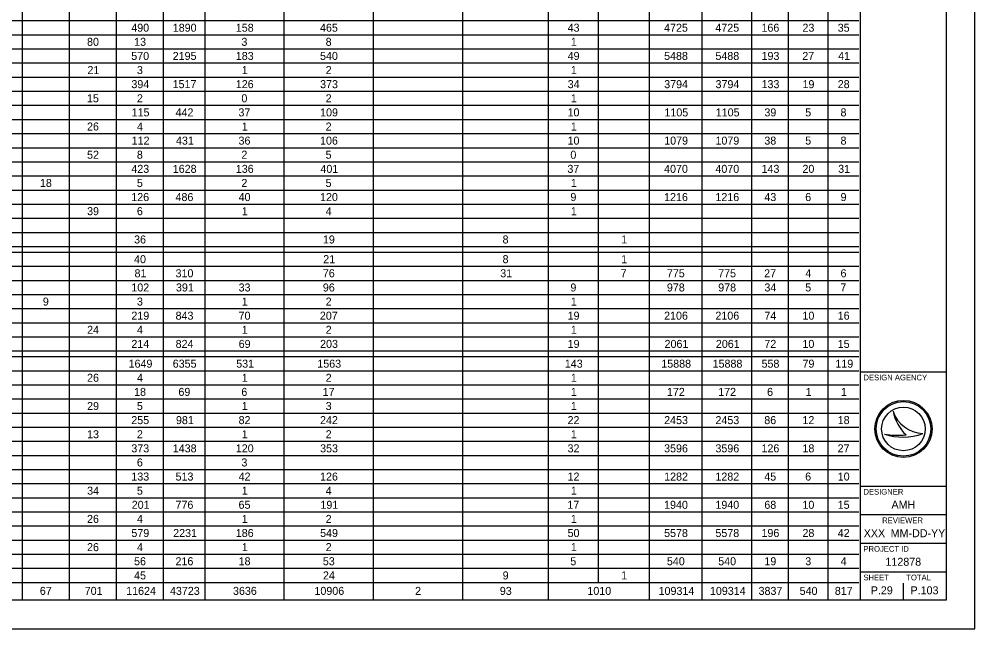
# Model space of a CAD drawing. Extents: x 0 to 34, y 0 to 22.
# Drawn here: x 17.28 to 34, y 0 to 10.67 of the extents above; entities that cross this region are included whole.
import ezdxf

# ---------------------------------------------------------------- set-up
doc = ezdxf.new("R2010")
doc.units = 0
for name, color, linetype in [('SH_Border', 7, 'Continuous'), ('SH_Cut_Line', 7, 'Continuous'), ('SH_Data', 7, 'Continuous'), ('SH_Text', 7, 'Continuous')]:
    doc.layers.add(name, color=color, linetype=linetype)

msp = doc.modelspace()

# ---------------------------------------------------------------- linework, layer by layer
at = {"layer": 'SH_Border'}
for p, q in [((32, 0.5), (32, 21.5)), ((32, 4.5), (33.5, 4.5)), ((32, 2.5), (33.5, 2.5)), ((32, 2), (33.5, 2)), ((32, 1.5), (33.5, 1.5)), ((32, 1), (33.5, 1))]:
    msp.add_line(p, q, dxfattribs=at)
msp.add_lwpolyline([(1.5, 21.5), (33.5, 21.5), (33.5, 0.5), (1.5, 0.5)], close=True, dxfattribs=at)
at = {"layer": 'SH_Cut_Line'}
msp.add_lwpolyline([(0, 0), (34, 0), (34, 22), (0, 22)], close=True, dxfattribs=at)
at = {"layer": 'SH_Data'}
for p, q in [((32.567, 3.81), (32.567, 3.81)), ((32.417, 3.41), (32.417, 3.41)), ((32.75, 3.5), (32.75, 3.5)), ((33.087, 3.419), (33.087, 3.419)), ((32.375, 0.675), (32.375, 0.675)), ((32.75, 0.5), (32.75, 0.8))]:
    msp.add_line(p, q, dxfattribs=at)
for radius in [0.5, 0.477, 0.477, 0.382]:
    msp.add_circle((32.75, 3.5), radius, dxfattribs=at)
for centre, radius, start, end in [((33.116, 3.998), 0.58, 198.9257, 198.9319), ((33.347, 3.97), 0.796, 191.6379, 191.6421), ((33.116, 3.998), 0.58, 198.9319, 267.1657), ((33.347, 3.97), 0.796, 191.6421, 226.0947), ((32.739, 4.37), 1.013, 251.4576, 290.0832), ((32.648, 4.654), 1.266, 259.4964, 259.4995), ((32.739, 4.37), 1.013, 251.4527, 251.4576), ((32.648, 4.654), 1.266, 259.4995, 276.6672)]:
    msp.add_arc(centre, radius, start, end, dxfattribs=at)
at = {"layer": 'SH_Text'}
for p, q in [((17.328, 21.187), (17.328, 0.516)), ((18.152, 21.187), (18.152, 0.516)), ((18.975, 21.187), (18.975, 0.516)), ((19.799, 21.187), (19.799, 0.516)), ((20.524, 21.187), (20.524, 0.516)), ((25.036, 21.187), (25.036, 0.516)), ((26.535, 21.187), (26.535, 0.516)), ((28.298, 21.187), (28.298, 0.516)), ((21.907, 20.907), (21.907, 0.516)), ((23.472, 20.907), (23.472, 0.516)), ((29.22, 20.907), (29.22, 0.516)), ((30.093, 20.907), (30.093, 0.516)), ((30.735, 20.907), (30.735, 0.516)), ((31.427, 20.907), (31.427, 0.516)), ((27.408, 19.227), (27.408, 0.813)), ((1.5, 10.646), (31.971, 10.646)), ((1.5, 10.399), (31.971, 10.399)), ((1.5, 10.152), (31.971, 10.152)), ((1.5, 9.905), (31.971, 9.905)), ((1.5, 9.658), (31.971, 9.658)), ((1.5, 9.411), (31.971, 9.411)), ((1.5, 9.164), (31.971, 9.164)), ((1.5, 8.916), (31.971, 8.916)), ((1.5, 8.669), (31.971, 8.669)), ((1.5, 8.422), (31.971, 8.422)), ((1.5, 8.175), (31.971, 8.175)), ((1.5, 7.928), (31.971, 7.928)), ((1.5, 7.681), (31.971, 7.681)), ((1.5, 7.434), (31.971, 7.434)), ((1.5, 7.187), (31.971, 7.187)), ((1.5, 6.94), (31.971, 6.94)), ((1.5, 6.693), (31.971, 6.693)), ((1.5, 6.594), (31.971, 6.594)), ((1.5, 6.347), (31.971, 6.347)), ((1.5, 6.1), (31.971, 6.1)), ((1.5, 5.853), (31.971, 5.853)), ((1.5, 5.606), (31.971, 5.606)), ((1.5, 5.359), (31.971, 5.359)), ((1.5, 5.112), (31.971, 5.112)), ((1.5, 4.865), (31.971, 4.865)), ((1.5, 4.766), (31.971, 4.766)), ((1.5, 4.519), (31.971, 4.519)), ((1.5, 4.272), (31.971, 4.272)), ((1.5, 4.025), (31.971, 4.025)), ((1.5, 3.778), (31.971, 3.778)), ((1.5, 3.531), (31.971, 3.531)), ((1.5, 3.284), (31.971, 3.284)), ((1.5, 3.036), (31.971, 3.036)), ((1.5, 2.789), (31.971, 2.789)), ((1.5, 2.542), (31.971, 2.542)), ((1.5, 2.295), (31.971, 2.295)), ((1.5, 2.048), (31.971, 2.048)), ((1.5, 1.801), (31.971, 1.801)), ((1.5, 1.554), (31.971, 1.554)), ((1.5, 1.307), (31.971, 1.307)), ((1.5, 1.06), (31.971, 1.06)), ((1.5, 0.813), (31.971, 0.813))]:
    msp.add_line(p, q, dxfattribs=at)

# ---------------------------------------------------------------- texts
at = {"layer": 'SH_Data'}
for s, height, p in [('DESIGN AGENCY', 0.1, (32.05, 4.35)), ('DESIGNER', 0.1, (32.05, 2.35)), ('AMH', 0.14, (32.541, 2.105)), ('REVIEWER', 0.1, (32.378, 1.85)), ('XXX', 0.14, (32.055, 1.605)), ('MM-DD-YY', 0.14, (32.526, 1.605)), ('PROJECT ID', 0.1, (32.05, 1.35)), ('112878', 0.14, (32.435, 1.105)), ('SHEET', 0.1, (32.05, 0.85)), ('TOTAL', 0.1, (32.8, 0.85)), ('P.29', 0.14, (32.178, 0.605)), ('P.103', 0.14, (32.874, 0.605))]:
    msp.add_text(s, height=height, dxfattribs=at).set_placement(p)
at = {"layer": 'SH_Text'}
for s, p in [('490', (19.239, 10.452)), ('1890', (19.965, 10.452)), ('158', (21.068, 10.452)), ('465', (22.541, 10.452)), ('43', (26.874, 10.452)), ('4725', (28.562, 10.452)), ('4725', (29.459, 10.452)), ('166', (30.266, 10.452)), ('23', (30.983, 10.452)), ('35', (31.6, 10.452)), ('80', (18.465, 10.205)), ('13', (19.289, 10.205)), ('3', (21.166, 10.205)), ('8', (22.64, 10.205)), ('1', (26.93, 10.205)), ('570', (19.239, 9.958)), ('2195', (19.964, 9.958)), ('183', (21.068, 9.958)), ('540', (22.542, 9.958)), ('49', (26.874, 9.958)), ('5488', (28.562, 9.958)), ('5488', (29.46, 9.958)), ('193', (30.267, 9.958)), ('27', (30.98, 9.958)), ('41', (31.608, 9.958)), ('21', (18.472, 9.711)), ('3', (19.338, 9.711)), ('1', (21.173, 9.711)), ('2', (22.64, 9.711)), ('1', (26.93, 9.711)), ('394', (19.241, 9.464)), ('1517', (19.962, 9.464)), ('126', (21.068, 9.464)), ('373', (22.543, 9.464)), ('34', (26.875, 9.464)), ('3794', (28.564, 9.464)), ('3794', (29.462, 9.464)), ('133', (30.267, 9.464)), ('19', (30.984, 9.464)), ('28', (31.6, 9.464)), ('15', (18.464, 9.217)), ('2', (19.338, 9.217)), ('0', (21.166, 9.217)), ('2', (22.64, 9.217)), ('1', (26.93, 9.217)), ('115', (19.245, 8.97)), ('442', (20.014, 8.97)), ('37', (21.114, 8.97)), ('109', (22.543, 8.97)), ('10', (26.873, 8.97)), ('1105', (28.568, 8.97)), ('1105', (29.466, 8.97)), ('39', (30.317, 8.97)), ('5', (31.031, 8.97)), ('8', (31.649, 8.97)), ('26', (18.465, 8.723)), ('2', (22.64, 8.723)), ('4', (19.339, 8.723)), ('1', (21.173, 8.723)), ('1', (26.93, 8.723)), ('112', (19.246, 8.476)), ('431', (20.021, 8.476)), ('36', (21.116, 8.476)), ('106', (22.542, 8.476)), ('10', (26.873, 8.476)), ('1079', (28.564, 8.476)), ('1079', (29.461, 8.476)), ('38', (30.316, 8.476)), ('5', (31.031, 8.476)), ('8', (31.649, 8.476)), ('52', (18.465, 8.229)), ('8', (19.337, 8.229)), ('2', (21.166, 8.229)), ('5', (22.639, 8.229)), ('0', (26.922, 8.229)), ('423', (19.24, 7.982)), ('1628', (19.965, 7.982)), ('136', (21.068, 7.982)), ('401', (22.549, 7.982)), ('37', (26.87, 7.982)), ('4070', (28.562, 7.982)), ('4070', (29.46, 7.982)), ('143', (30.267, 7.982)), ('20', (30.983, 7.982)), ('31', (31.608, 7.982)), ('18', (17.641, 7.735)), ('5', (19.337, 7.735)), ('2', (21.166, 7.735)), ('5', (22.639, 7.735)), ('1', (26.93, 7.735)), ('126', (19.239, 7.488)), ('486', (20.013, 7.488)), ('40', (21.117, 7.488)), ('120', (22.542, 7.488)), ('9', (26.923, 7.488)), ('1216', (28.562, 7.488)), ('1216', (29.46, 7.488)), ('43', (30.316, 7.488)), ('6', (31.031, 7.488)), ('9', (31.65, 7.488)), ('39', (18.466, 7.241)), ('6', (19.337, 7.241)), ('1', (21.173, 7.241)), ('4', (22.642, 7.241)), ('1', (26.93, 7.241)), ('36', (19.288, 6.746)), ('19', (22.592, 6.746)), ('8', (25.736, 6.746)), ('1', (27.811, 6.746)), ('40', (19.288, 6.401)), ('21', (22.598, 6.401)), ('8', (25.736, 6.401)), ('1', (27.811, 6.401)), ('81', (19.296, 6.154)), ('310', (20.014, 6.154)), ('76', (22.591, 6.154)), ('31', (25.695, 6.154)), ('7', (27.801, 6.154)), ('775', (28.611, 6.154)), ('775', (29.508, 6.154)), ('27', (30.313, 6.154)), ('4', (31.033, 6.154)), ('6', (31.649, 6.154)), ('102', (19.24, 5.906)), ('391', (20.021, 5.906)), ('33', (21.117, 5.906)), ('96', (22.591, 5.906)), ('9', (26.923, 5.906)), ('978', (28.611, 5.906)), ('978', (29.509, 5.906)), ('34', (30.317, 5.906)), ('5', (31.031, 5.906)), ('7', (31.646, 5.906)), ('9', (17.692, 5.659)), ('3', (19.338, 5.659)), ('1', (21.173, 5.659)), ('2', (22.64, 5.659)), ('1', (26.93, 5.659)), ('219', (19.241, 5.412)), ('843', (20.014, 5.412)), ('70', (21.117, 5.412)), ('207', (22.539, 5.412)), ('19', (26.874, 5.412)), ('2106', (28.562, 5.412)), ('2106', (29.46, 5.412)), ('74', (30.317, 5.412)), ('10', (30.983, 5.412)), ('16', (31.6, 5.412)), ('24', (18.467, 5.165)), ('4', (19.339, 5.165)), ('1', (21.173, 5.165)), ('2', (22.64, 5.165)), ('1', (26.93, 5.165)), ('214', (19.241, 4.918)), ('824', (20.015, 4.918)), ('69', (21.118, 4.918)), ('203', (22.543, 4.918)), ('19', (26.874, 4.918)), ('2061', (28.57, 4.918)), ('2061', (29.468, 4.918)), ('72', (30.316, 4.918)), ('10', (30.983, 4.918)), ('15', (31.6, 4.918)), ('1649', (19.192, 4.572)), ('6355', (19.964, 4.572)), ('531', (21.075, 4.572)), ('1563', (22.494, 4.572)), ('143', (26.825, 4.572)), ('15888', (28.513, 4.572)), ('15888', (29.411, 4.572)), ('558', (30.267, 4.572)), ('79', (30.984, 4.572)), ('119', (31.559, 4.572)), ('26', (18.465, 4.325)), ('4', (19.339, 4.325)), ('1', (21.173, 4.325)), ('2', (22.64, 4.325)), ('1', (26.93, 4.325)), ('18', (19.288, 4.078)), ('69', (20.064, 4.078)), ('6', (21.165, 4.078)), ('17', (22.588, 4.078)), ('1', (26.93, 4.078)), ('172', (28.612, 4.078)), ('172', (29.509, 4.078)), ('6', (30.364, 4.078)), ('1', (31.039, 4.078)), ('1', (31.657, 4.078)), ('29', (18.466, 3.831)), ('5', (19.337, 3.831)), ('1', (21.173, 3.831)), ('3', (22.64, 3.831)), ('1', (26.93, 3.831)), ('255', (19.239, 3.584)), ('981', (20.021, 3.584)), ('82', (21.117, 3.584)), ('242', (22.542, 3.584)), ('22', (26.873, 3.584)), ('2453', (28.563, 3.584)), ('2453', (29.461, 3.584)), ('86', (30.315, 3.584)), ('12', (30.983, 3.584)), ('18', (31.6, 3.584)), ('13', (18.466, 3.337)), ('2', (19.338, 3.337)), ('1', (21.173, 3.337)), ('2', (22.64, 3.337)), ('1', (26.93, 3.337)), ('373', (19.24, 3.09)), ('1438', (19.965, 3.09)), ('120', (21.068, 3.09)), ('353', (22.543, 3.09)), ('32', (26.873, 3.09)), ('3596', (28.562, 3.09)), ('3596', (29.46, 3.09)), ('126', (30.266, 3.09)), ('18', (30.983, 3.09)), ('27', (31.598, 3.09)), ('6', (19.337, 2.843)), ('3', (21.166, 2.843)), ('133', (19.24, 2.596)), ('513', (20.014, 2.596)), ('42', (21.117, 2.596)), ('126', (22.542, 2.596)), ('12', (26.873, 2.596)), ('1282', (28.563, 2.596)), ('1282', (29.46, 2.596)), ('45', (30.315, 2.596)), ('6', (31.031, 2.596)), ('10', (31.6, 2.596)), ('34', (18.467, 2.349)), ('5', (19.337, 2.349)), ('1', (21.173, 2.349)), ('4', (22.642, 2.349)), ('1', (26.93, 2.349)), ('201', (19.247, 2.102)), ('776', (20.013, 2.102)), ('65', (21.116, 2.102)), ('191', (22.549, 2.102)), ('17', (26.87, 2.102)), ('1940', (28.562, 2.102)), ('1940', (29.46, 2.102)), ('68', (30.316, 2.102)), ('10', (30.983, 2.102)), ('15', (31.6, 2.102)), ('26', (18.465, 1.855)), ('4', (19.339, 1.855)), ('1', (21.173, 1.855)), ('2', (22.64, 1.855)), ('1', (26.93, 1.855)), ('579', (19.241, 1.608)), ('2231', (19.972, 1.608)), ('186', (21.068, 1.608)), ('549', (22.543, 1.608)), ('50', (26.873, 1.608)), ('5578', (28.562, 1.608)), ('5578', (29.46, 1.608)), ('196', (30.266, 1.608)), ('28', (30.983, 1.608)), ('42', (31.6, 1.608)), ('26', (18.465, 1.361)), ('4', (19.339, 1.361)), ('1', (21.173, 1.361)), ('2', (22.64, 1.361)), ('1', (26.93, 1.361)), ('56', (19.288, 1.114)), ('216', (20.013, 1.114)), ('18', (21.117, 1.114)), ('53', (22.591, 1.114)), ('5', (26.921, 1.114)), ('540', (28.611, 1.114)), ('540', (29.509, 1.114)), ('19', (30.317, 1.114)), ('3', (31.032, 1.114)), ('4', (31.651, 1.114)), ('45', (19.288, 0.866)), ('24', (22.593, 0.866)), ('9', (25.737, 0.866)), ('1', (27.811, 0.866)), ('67', (17.639, 0.595)), ('701', (18.424, 0.595)), ('11624', (19.15, 0.595)), ('43723', (19.916, 0.595)), ('3636', (21.019, 0.595)), ('10906', (22.444, 0.595)), ('2', (24.205, 0.595)), ('93', (25.688, 0.595)), ('1010', (27.22, 0.595)), ('109314', (28.466, 0.595)), ('109314', (29.364, 0.595)), ('3837', (30.215, 0.595)), ('540', (30.934, 0.595)), ('817', (31.549, 0.595))]:
    msp.add_text(s, height=0.14, dxfattribs=at).set_placement(p)

doc.saveas('drawing.dxf')
